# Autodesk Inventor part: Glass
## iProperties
Created: 2007-11
Part Number: Glass
Document SubType Name: Modeling
Designer: CM
Density: 1 g/cm^3
Mass: 0.377597 g
Surface Area: 4.35483 cm^2
Volume: 0.377597 cm^3
Author: CM
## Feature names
1. Revolution1
